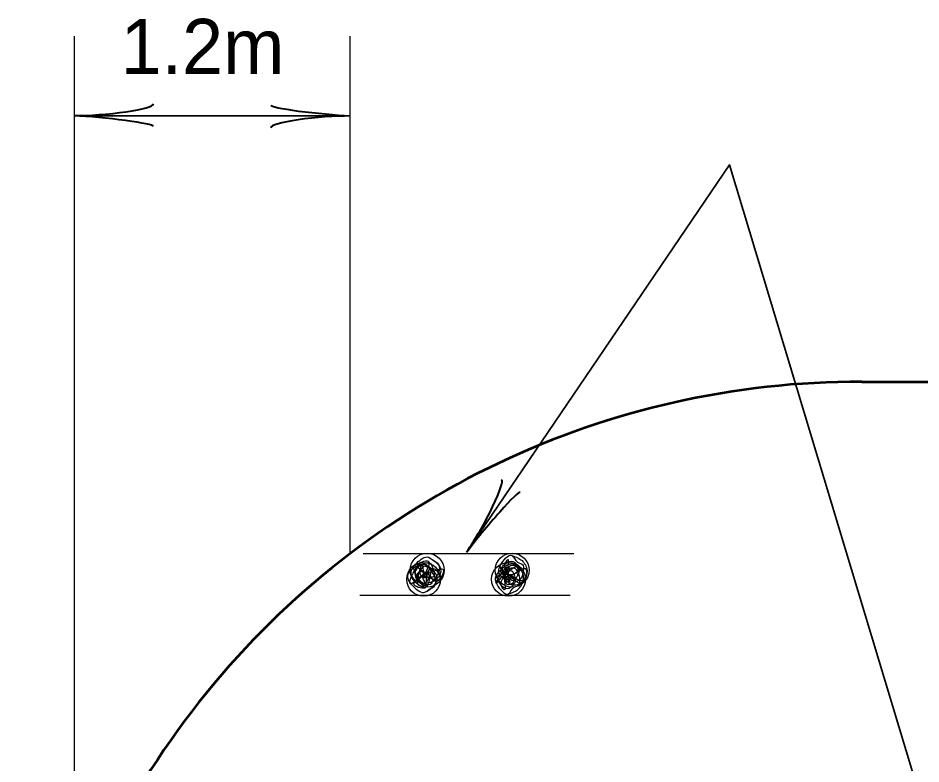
# Model space of a CAD drawing. Extents: x -198 to 658, y -402 to 142.
# Drawn here: x 469.54 to 508.89, y -71.01 to -38.52 of the extents above; entities that cross this region are included whole.
import ezdxf
from ezdxf.enums import TextEntityAlignment as Align

# ---------------------------------------------------------------- set-up
doc = ezdxf.new("R2010")
doc.units = 0
doc.header["$LTSCALE"] = 0.96
doc.layers.add('1', color=7, linetype='Continuous', lineweight=35)
doc.layers.add('4', color=7, linetype='Continuous', lineweight=25)

msp = doc.modelspace()

# ---------------------------------------------------------------- linework, layer by layer
at = {"layer": '1', "lineweight": 25}
for p, q in [((471.9848, -39.3022), (471.9848, -77.8663)), ((484.0057, -39.3022), (484.0057, -61.849)), ((493.7619, -61.8582), (484.582, -61.8582)), ((493.6083, -63.673), (484.4284, -63.673))]:
    msp.add_line(p, q, dxfattribs=at)
at = {"layer": '1'}
msp.add_line((484.0057, -42.7752), (471.9848, -42.7752), dxfattribs=at)
at = {"layer": '1', "lineweight": 53}
msp.add_line((506.3064, -54.3638), (562.2004, -54.3638), dxfattribs=at)
at = {"layer": '1'}
msp.add_lwpolyline([(489.1016, -61.7749), (500.551, -44.9095), (508.5282, -71.3424)], dxfattribs=at)
at = {"layer": '1', "lineweight": 53}
msp.add_arc((506.207, -91.0305), 36.6668, 89.84467, 191.96498, dxfattribs=at)
at = {"layer": '1', "lineweight": 40}
for centre, major_axis, ratio, start_param, end_param in [((473.2942, -42.4436), (-2.1428, -0.1874), 0.122415, 0.8963533, 3.1415927), ((482.6611, -42.5213), (2.1077, -0.2108), 0.07063, 3.1407148, 5.41811), ((473.3294, -43.0291), (-2.1077, 0.2108), 0.07063, 3.1407148, 5.41811), ((482.6963, -43.1068), (2.1428, 0.1874), 0.122415, 0.8963533, 3.1415927), ((489.5628, -60.5053), (-1.0485, -1.8781), 0.122415, 0.8963533, 3.1415927), ((489.5628, -60.5053), (-1.0485, -1.8781), 0.122415, 0.8963533, 3.1415927), ((490.0669, -60.8051), (1.3582, 1.6255), 0.07063, 6.2823074, 8.5597026), ((490.0669, -60.8051), (1.3582, 1.6255), 0.07063, 6.2823074, 8.5597026)]:
    msp.add_ellipse(centre, major_axis=major_axis, ratio=ratio, start_param=start_param, end_param=end_param, dxfattribs=at)
at = {"layer": '1', "lineweight": 25}
for points in [[(487.2723, -63.5291), (487.6324, -63.2771), (487.8124, -62.9171), (487.7044, -62.665), (487.3083, -62.413), (486.9123, -62.413), (486.5164, -62.809), (486.7684, -63.277), (487.2723, -63.5291), (487.4884, -63.385), (487.6683, -63.2771), (487.7404, -62.953), (487.4884, -62.5211), (487.3444, -62.3411), (486.8404, -62.629), (486.9123, -62.9891), (486.9843, -63.205), (487.1284, -63.2771), (487.3443, -63.2771), (487.4523, -63.061), (487.4884, -62.6651), (487.2363, -62.6651), (487.0564, -62.6291), (486.9123, -62.8451), (487.1644, -63.1691), (487.3804, -63.025), (487.4164, -62.881), (487.1644, -62.8451), (487.2004, -62.773), (486.6604, -63.169), (487.1284, -62.3051), (487.2363, -62.809), (487.5603, -62.485), (487.9204, -62.9891), (487.1644, -62.8451), (487.3083, -63.3131), (486.8044, -63.2051), (487.1644, -62.8451)], [(487.4259, -62.0021), (487.786, -62.2541), (487.966, -62.6141), (487.858, -62.8662), (487.4619, -63.1182), (487.0659, -63.1182), (486.67, -62.7222), (486.922, -62.2542), (487.4259, -62.0021), (487.642, -62.1462), (487.8219, -62.2541), (487.894, -62.5782), (487.642, -63.0101), (487.498, -63.1901), (486.994, -62.9022), (487.0659, -62.5421), (487.1379, -62.3262), (487.282, -62.2541), (487.4979, -62.2541), (487.6059, -62.4702), (487.642, -62.8661), (487.3899, -62.8661), (487.21, -62.9021), (487.0659, -62.6861), (487.318, -62.3621), (487.534, -62.5062), (487.57, -62.6502), (487.318, -62.6861), (487.354, -62.7582), (486.814, -62.3622), (487.282, -63.2261), (487.3899, -62.7222), (487.7139, -63.0462), (488.074, -62.5421), (487.318, -62.6861), (487.4619, -62.2181), (486.958, -62.3261), (487.318, -62.6861)], [(491.0619, -61.9302), (491.458, -62.1102), (491.71, -62.5062), (491.638, -62.9381), (491.1699, -63.2261), (490.738, -62.9742), (490.4859, -62.6141), (490.558, -62.3622), (491.0619, -61.9302), (491.314, -62.2181), (491.53, -62.3261), (491.566, -62.5421), (491.314, -63.0462), (491.0619, -63.0101), (490.8819, -62.8661), (490.5939, -62.6862), (490.8099, -62.2542), (491.0979, -62.1822), (491.278, -62.3261), (491.3859, -62.5421), (491.3139, -62.7582), (491.242, -62.9022), (490.8819, -62.7942), (490.954, -62.5422), (490.9539, -62.3982), (491.242, -62.3982), (491.314, -62.6141), (490.9179, -62.7582), (490.846, -62.7222), (490.522, -62.3982), (490.9899, -63.0822), (490.882, -62.7582), (491.422, -63.1182), (491.674, -62.5062), (490.9179, -62.7582), (490.882, -62.1102), (490.7739, -62.2541), (490.9179, -62.7582)], [(490.9083, -63.601), (491.3044, -63.421), (491.5564, -63.025), (491.4844, -62.5931), (491.0163, -62.3051), (490.5844, -62.557), (490.3323, -62.9171), (490.4044, -63.169), (490.9083, -63.601), (491.1604, -63.3131), (491.3764, -63.2051), (491.4124, -62.9891), (491.1604, -62.485), (490.9083, -62.5211), (490.7283, -62.6651), (490.4403, -62.845), (490.6563, -63.277), (490.9443, -63.349), (491.1244, -63.2051), (491.2323, -62.9891), (491.1603, -62.773), (491.0884, -62.629), (490.7283, -62.737), (490.8004, -62.989), (490.8003, -63.133), (491.0884, -63.133), (491.1604, -62.9171), (490.7643, -62.773), (490.6924, -62.809), (490.3684, -63.133), (490.8363, -62.449), (490.7284, -62.773), (491.2684, -62.413), (491.5204, -63.025), (490.7643, -62.773), (490.7284, -63.421), (490.6203, -63.2771), (490.7643, -62.773)]]:
    msp.add_spline(points, degree=3, dxfattribs=at)
at = {"layer": '4'}
for centre in [(487.3682, -62.5666), (491.0704, -62.5664), (487.2146, -62.9646), (490.9168, -62.9648)]:
    msp.add_circle(centre, 0.738, dxfattribs=at)

# ---------------------------------------------------------------- texts
at = {"layer": '1'}
msp.add_text('1.2m', height=2.4, dxfattribs=at).set_placement((477.5811, -40.9562), align=Align.CENTER)

doc.saveas('drawing.dxf')
